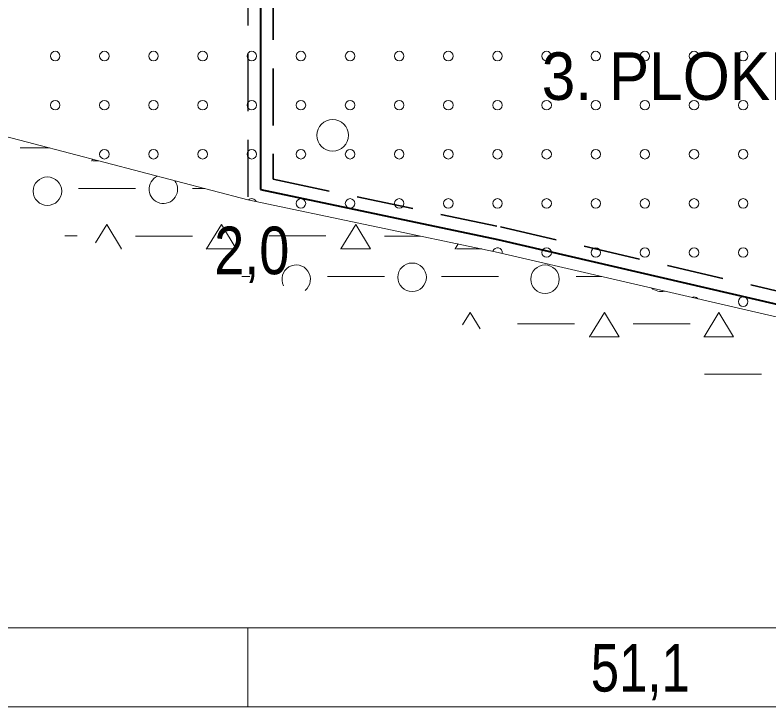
# Model space of a CAD drawing. Extents: x 640104 to 640970, y 6442278 to 6442689.
# Drawn here: x 640807.48 to 640855.03, y 6442488.94 to 6442532.6 of the extents above; entities that cross this region are included whole.
import ezdxf
from ezdxf.enums import TextEntityAlignment as Align

# ---------------------------------------------------------------- set-up
doc = ezdxf.new("R2010")
doc.units = 0
doc.header["$LTSCALE"] = 1.2
doc.linetypes.add('MEDIUM_DASHED', pattern=[4.5, 3, -1.5])
for name, color, linetype, lineweight in [('30', 7, 'Continuous', 13), ('31', 7, 'Continuous', 13), ('32', 7, 'Continuous', 25), ('35', 7, 'Continuous', 35), ('43', 7, 'Continuous', 13), ('46', 7, 'Continuous', 13), ('47', 7, 'Continuous', 13)]:
    doc.layers.add(name, color=color, linetype=linetype, lineweight=lineweight)

msp = doc.modelspace()

# ---------------------------------------------------------------- linework, layer by layer
at = {"layer": '30'}
for p, q in [((640524.54, 6442493.94), (640955.05, 6442493.94)), ((640822.17, 6442493.94), (640822.17, 6442488.94)), ((640524.54, 6442488.94), (640955.05, 6442488.94))]:
    msp.add_line(p, q, dxfattribs=at)
at = {"layer": '31'}
msp.add_lwpolyline([(640553.71, 6442558.56), (640570.07, 6442558.94), (640649.85, 6442563.98), (640763.79, 6442536.22), (640808.67, 6442524.48), (640822.17, 6442520.94), (640837.77, 6442517.67), (640873.2, 6442509.45), (640884.27, 6442508.94), (640895.27, 6442508.94), (640947.47, 6442510.44), (640955.05, 6442510.44)], dxfattribs=at)
at = {"layer": '32', "linetype": 'MEDIUM_DASHED'}
msp.add_line((640822.17, 6442540.94), (640822.17, 6442520.94), dxfattribs=at)
at = {"layer": '35', "lineweight": 40}
msp.add_line((640822.97, 6442540.94), (640822.97, 6442521.59), dxfattribs=at)
at = {"layer": '35', "linetype": 'MEDIUM_DASHED'}
msp.add_line((640823.77, 6442540.04), (640823.77, 6442522.24), dxfattribs=at)
msp.add_lwpolyline([(640823.77, 6442522.24), (640838.11, 6442519.23), (640873.42, 6442511.04), (640883.47, 6442510.58)], dxfattribs=at)
at = {"layer": '35', "lineweight": 40}
msp.add_lwpolyline([(640822.97, 6442521.59), (640837.94, 6442518.45), (640873.31, 6442510.24), (640884.29, 6442509.74), (640895.3, 6442509.74), (640946.67, 6442511.32)], dxfattribs=at)
at = {"layer": '43'}
for centre in [(640810.011, 6442530.018), (640813.111, 6442530.018), (640816.211, 6442530.018), (640819.311, 6442530.018), (640822.411, 6442530.018), (640825.511, 6442530.018), (640828.611, 6442530.018), (640831.711, 6442530.018), (640834.811, 6442530.018), (640837.911, 6442530.018), (640841.011, 6442530.018), (640844.111, 6442530.018), (640847.211, 6442530.018), (640850.311, 6442530.018), (640853.411, 6442530.018), (640810.011, 6442526.918), (640813.111, 6442526.918), (640816.211, 6442526.918), (640819.311, 6442526.918), (640822.411, 6442526.918), (640825.511, 6442526.918), (640828.611, 6442526.918), (640831.711, 6442526.918), (640834.811, 6442526.918), (640837.911, 6442526.918), (640841.011, 6442526.918), (640844.111, 6442526.918), (640847.211, 6442526.918), (640850.311, 6442526.918), (640853.411, 6442526.918), (640813.111, 6442523.818), (640816.211, 6442523.818), (640819.311, 6442523.818), (640822.411, 6442523.818), (640825.511, 6442523.818), (640828.611, 6442523.818), (640831.711, 6442523.818), (640834.811, 6442523.818), (640837.911, 6442523.818), (640841.011, 6442523.818), (640844.111, 6442523.818), (640847.211, 6442523.818), (640850.311, 6442523.818), (640853.411, 6442523.818), (640825.511, 6442520.718), (640828.611, 6442520.718), (640831.711, 6442520.718), (640834.811, 6442520.718), (640837.911, 6442520.718), (640841.011, 6442520.718), (640844.111, 6442520.718), (640847.211, 6442520.718), (640850.311, 6442520.718), (640853.411, 6442520.718), (640841.011, 6442517.618), (640844.111, 6442517.618), (640847.211, 6442517.618), (640850.311, 6442517.618), (640853.411, 6442517.618), (640853.411, 6442514.518)]:
    msp.add_circle(centre, 0.3, dxfattribs=at)
for centre, start, end in [((640822.411, 6442520.718), 22.3498, 133.9728), ((640837.911, 6442517.618), 350.6553, 163.8205), ((640850.311, 6442514.518), 38.5591, 115.3024)]:
    msp.add_arc(centre, 0.3, start, end, dxfattribs=at)
at = {"layer": '46'}
for p, q in [((640809.66, 6442524.22), (640807.79, 6442524.22)), ((640812.75, 6442523.41), (640812.4, 6442523.41)), ((640815.08, 6442521.66), (640811.48, 6442521.66)), ((640819.44, 6442521.66), (640818.68, 6442521.66)), ((640811.39, 6442518.67), (640810.62, 6442518.67)), ((640818.68, 6442518.66), (640815.08, 6442518.66)), ((640827.08, 6442518.67), (640823.48, 6442518.67)), ((640833.04, 6442518.66), (640830.78, 6442518.66)), ((640836.92, 6442517.85), (640835.32, 6442517.86)), ((640822.28, 6442516.1), (640821.78, 6442516.1)), ((640830.78, 6442516.11), (640827.18, 6442516.11)), ((640837.98, 6442516.1), (640834.38, 6442516.1)), ((640844.5, 6442516.11), (640842.87, 6442516.11)), ((640842.78, 6442513.11), (640839.18, 6442513.11)), ((640850.07, 6442513.11), (640846.47, 6442513.11)), ((640854.57, 6442509.95), (640850.97, 6442509.95))]:
    msp.add_line(p, q, dxfattribs=at)
for points in [[(640812.32, 6442523.39), (640812.33, 6442523.41), (640812.38, 6442523.51)], [(640812.55, 6442518.22), (640813.27, 6442519.39), (640814.2, 6442517.85), (640814.16, 6442517.85)], [(640819.54, 6442517.83), (640819.55, 6442517.86), (640820.49, 6442519.39), (640821.42, 6442517.85), (640819.62, 6442517.86)], [(640828.02, 6442517.83), (640828.02, 6442517.86), (640828.97, 6442519.39), (640829.9, 6442517.85), (640828.1, 6442517.86)], [(640835.24, 6442517.83), (640835.24, 6442517.86), (640835.43, 6442518.16)], [(640835.7, 6442513.05), (640836.19, 6442513.83), (640836.81, 6442512.81)], [(640843.71, 6442512.28), (640843.72, 6442512.3), (640844.66, 6442513.83), (640845.59, 6442512.29), (640843.79, 6442512.3)], [(640850.93, 6442512.28), (640850.94, 6442512.3), (640851.88, 6442513.83), (640852.81, 6442512.29), (640851.01, 6442512.3)]]:
    msp.add_lwpolyline(points, dxfattribs=at)
for centre in [(640809.519, 6442521.489), (640832.527, 6442516.056), (640840.909, 6442515.934)]:
    msp.add_circle(centre, 0.9, dxfattribs=at)
for centre, start, end in [((640816.832, 6442521.611), 113.6228, 36.9903), ((640825.214, 6442515.934), 308.3198, 206.9552), ((640848.222, 6442516.056), 228.4031, 285.4584)]:
    msp.add_arc(centre, 0.9, start, end, dxfattribs=at)
at = {"layer": '47'}
msp.add_circle((640827.513, 6442525.014), 1, dxfattribs=at)

# ---------------------------------------------------------------- texts
at = {"layer": '30', "width": 0.8}
msp.add_text('51,1', height=3, dxfattribs=at).set_placement((640846.92, 6442489.91), align=Align.CENTER)
at = {"layer": '32', "width": 0.85}
msp.add_text('2,0', height=3, dxfattribs=at).set_placement((640822.41, 6442516.25), align=Align.CENTER)
at = {"layer": '35', "width": 0.95}
msp.add_text('3. PLOKK', height=3, dxfattribs=at).set_placement((640849.175, 6442527.25), align=Align.CENTER)

doc.saveas('drawing.dxf')
